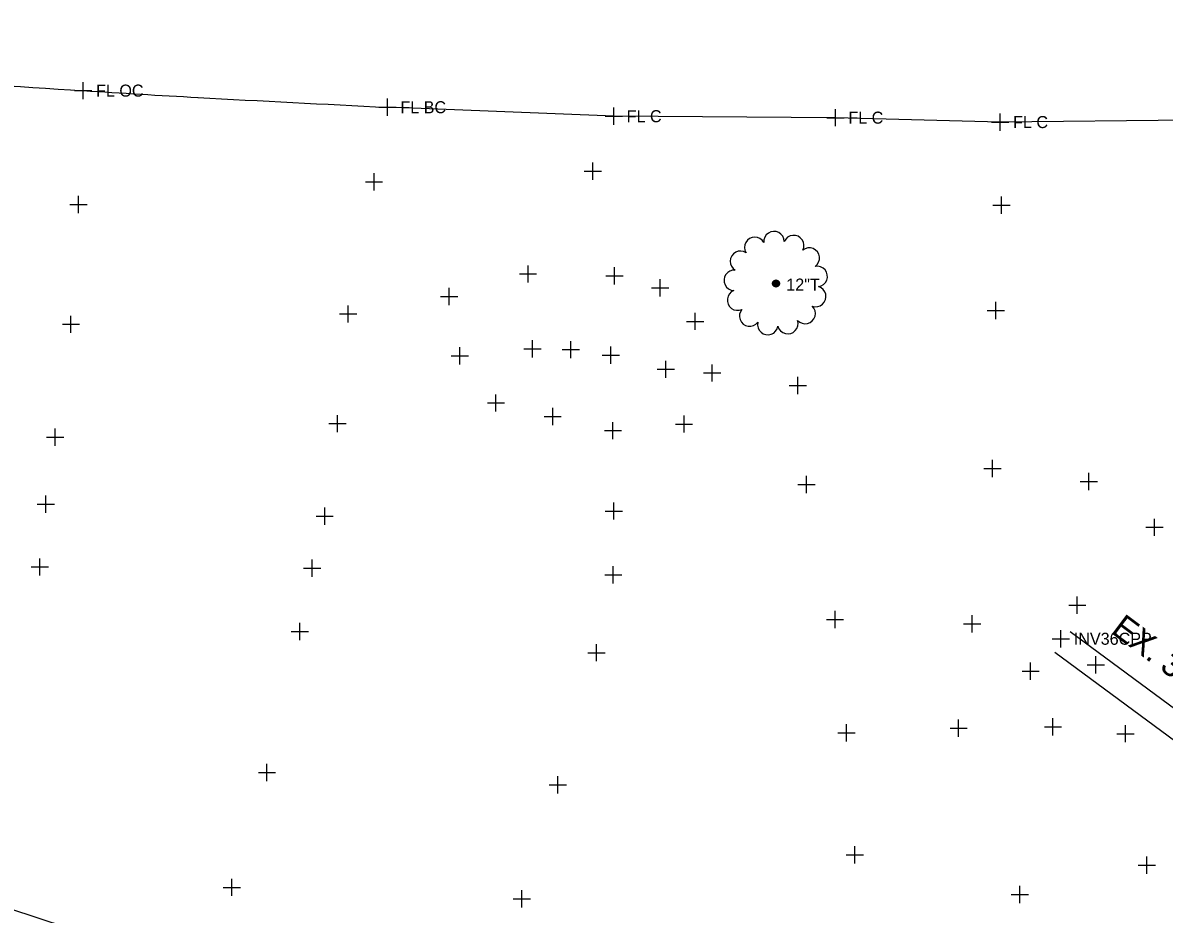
# Model space of a CAD drawing. Extents: x 1324236 to 1326110, y 459090 to 460782.
# Drawn here: x 1325183.3 to 1325315.8, y 460409.8 to 460513.2 of the extents above; entities that cross this region are included whole.
import ezdxf

# ---------------------------------------------------------------- set-up
doc = ezdxf.new("R2010")
doc.units = 0
for name, color, linetype in [('DV_X_Property_Line', 7, 'Continuous'), ('PM_X_CL_Double_Solid', 7, 'Continuous'), ('PV_X_Shoulder_Aggregate', 7, 'Continuous'), ('RW_X_CL', 7, 'Continuous'), ('RW_X_Esmt_SH', 7, 'Continuous'), ('UT_X_Telecom', 7, 'Continuous'), ('VG_X_Cells', 7, 'Continuous'), ('VG_X_Flower_Bed', 7, 'Continuous')]:
    doc.layers.add(name, color=color, linetype=linetype)

msp = doc.modelspace()

# ---------------------------------------------------------------- linework, layer by layer
at = {"layer": 'DV_X_Property_Line'}
for p, q in [((1325303.82, 460440.73), (1325303.82, 460442.73)), ((1325302.82, 460441.73), (1325304.82, 460441.73))]:
    msp.add_line(p, q, dxfattribs=at)
at = {"layer": 'PM_X_CL_Double_Solid'}
for p, q in [((1325251.91, 460502.37), (1325225.64, 460503.41)), ((1325277.65, 460502.2), (1325251.91, 460502.37)), ((1325296.77, 460501.69), (1325277.65, 460502.2)), ((1325326.93, 460502), (1325296.77, 460501.69))]:
    msp.add_line(p, q, dxfattribs=at)
for centre, radius, start, end in [((1333068.62, 583041.15), 122788.82, 266.3103858, 266.3212962), ((1325279.09, 461886.04), 1383.55, 266.3213, 266.87412), ((1325409.07, 464266.24), 3767.3, 266.87412, 267.20913)]:
    msp.add_arc(centre, radius, start, end, dxfattribs=at)
at = {"layer": 'PV_X_Shoulder_Aggregate'}
msp.add_lwpolyline([(1325286.15, 460376.13), (1325267.35, 460382.9), (1325236.36, 460392.86), (1325205.04, 460402.74), (1325175.07, 460412.61), (1325145.55, 460421.9), (1325113.81, 460432.03), (1325082.13, 460441.54), (1325051.05, 460449.76), (1325019.35, 460459.28), (1324987.54, 460468.89), (1324956.75, 460477.62), (1324924.35, 460486.71), (1324893.18, 460495.82), (1324861.31, 460505.68), (1324828.49, 460513.21)], dxfattribs=at)
at = {"layer": 'RW_X_CL'}
for p, q in [((1325249.47, 460494.98), (1325249.47, 460496.98)), ((1325224.08, 460493.75), (1325224.08, 460495.75)), ((1325248.47, 460495.98), (1325250.47, 460495.98)), ((1325223.08, 460494.75), (1325225.08, 460494.75)), ((1325189.78, 460491.13), (1325189.78, 460493.13)), ((1325296.93, 460491.04), (1325296.93, 460493.04)), ((1325188.78, 460492.13), (1325190.78, 460492.13)), ((1325295.93, 460492.04), (1325297.93, 460492.04)), ((1325241.96, 460483.06), (1325241.96, 460485.06)), ((1325251.99, 460482.85), (1325251.99, 460484.85)), ((1325240.96, 460484.06), (1325242.96, 460484.06)), ((1325250.99, 460483.85), (1325252.99, 460483.85)), ((1325257.3, 460481.45), (1325257.3, 460483.45)), ((1325232.81, 460480.46), (1325232.81, 460482.46)), ((1325256.3, 460482.45), (1325258.3, 460482.45)), ((1325231.81, 460481.46), (1325233.81, 460481.46)), ((1325296.27, 460478.83), (1325296.27, 460480.83)), ((1325221.07, 460478.42), (1325221.07, 460480.42)), ((1325261.37, 460477.56), (1325261.37, 460479.56)), ((1325295.27, 460479.83), (1325297.27, 460479.83)), ((1325187.9, 460478.22), (1325189.9, 460478.22)), ((1325188.9, 460477.22), (1325188.9, 460479.22)), ((1325220.07, 460479.42), (1325222.07, 460479.42)), ((1325260.37, 460478.56), (1325262.37, 460478.56)), ((1325234.03, 460473.56), (1325234.03, 460475.56)), ((1325242.48, 460474.37), (1325242.48, 460476.37)), ((1325246.93, 460474.28), (1325246.93, 460476.28)), ((1325251.56, 460473.63), (1325251.56, 460475.63)), ((1325233.03, 460474.56), (1325235.03, 460474.56)), ((1325241.48, 460475.37), (1325243.48, 460475.37)), ((1325245.93, 460475.28), (1325247.93, 460475.28)), ((1325250.56, 460474.63), (1325252.56, 460474.63)), ((1325256.97, 460473), (1325258.97, 460473)), ((1325257.97, 460472), (1325257.97, 460474)), ((1325263.35, 460471.57), (1325263.35, 460473.57)), ((1325262.35, 460472.57), (1325264.35, 460472.57)), ((1325273.27, 460470.12), (1325273.27, 460472.12)), ((1325272.27, 460471.12), (1325274.27, 460471.12)), ((1325237.24, 460469.09), (1325239.24, 460469.09)), ((1325238.24, 460468.09), (1325238.24, 460470.09)), ((1325219.85, 460465.69), (1325219.85, 460467.69)), ((1325243.82, 460467.52), (1325245.82, 460467.52)), ((1325244.82, 460466.52), (1325244.82, 460468.52)), ((1325260.07, 460465.65), (1325260.07, 460467.65)), ((1325218.85, 460466.69), (1325220.85, 460466.69)), ((1325251.82, 460464.88), (1325251.82, 460466.88)), ((1325259.07, 460466.65), (1325261.07, 460466.65)), ((1325186.07, 460465.13), (1325188.07, 460465.13)), ((1325187.07, 460464.13), (1325187.07, 460466.13)), ((1325250.82, 460465.88), (1325252.82, 460465.88)), ((1325295.87, 460460.5), (1325295.87, 460462.5)), ((1325294.87, 460461.5), (1325296.87, 460461.5)), ((1325307.07, 460458.98), (1325307.07, 460460.98)), ((1325273.28, 460459.63), (1325275.28, 460459.63)), ((1325274.28, 460458.63), (1325274.28, 460460.63)), ((1325306.07, 460459.98), (1325308.07, 460459.98)), ((1325185.97, 460456.34), (1325185.97, 460458.34)), ((1325184.97, 460457.34), (1325186.97, 460457.34)), ((1325218.35, 460454.96), (1325218.35, 460456.96)), ((1325251.93, 460455.55), (1325251.93, 460457.55)), ((1325217.35, 460455.96), (1325219.35, 460455.96)), ((1325250.93, 460456.55), (1325252.93, 460456.55)), ((1325314.68, 460453.66), (1325314.68, 460455.66)), ((1325313.68, 460454.66), (1325315.68, 460454.66)), ((1325185.29, 460449.06), (1325185.29, 460451.06)), ((1325216.91, 460448.91), (1325216.91, 460450.91)), ((1325184.29, 460450.06), (1325186.29, 460450.06)), ((1325215.91, 460449.91), (1325217.91, 460449.91)), ((1325250.86, 460449.15), (1325252.86, 460449.15)), ((1325251.86, 460448.15), (1325251.86, 460450.15)), ((1325305.73, 460444.62), (1325305.73, 460446.62)), ((1325277.6, 460442.97), (1325277.6, 460444.97)), ((1325304.73, 460445.62), (1325306.73, 460445.62)), ((1325276.6, 460443.97), (1325278.6, 460443.97)), ((1325293.52, 460442.45), (1325293.52, 460444.45)), ((1325214.46, 460442.58), (1325216.46, 460442.58)), ((1325215.46, 460441.58), (1325215.46, 460443.58)), ((1325292.52, 460443.45), (1325294.52, 460443.45)), ((1325249.91, 460439.11), (1325249.91, 460441.11)), ((1325248.91, 460440.11), (1325250.91, 460440.11)), ((1325307.88, 460437.7), (1325307.88, 460439.7)), ((1325300.31, 460436.98), (1325300.31, 460438.98)), ((1325306.88, 460438.7), (1325308.88, 460438.7)), ((1325299.31, 460437.98), (1325301.31, 460437.98)), ((1325278.92, 460429.81), (1325278.92, 460431.81)), ((1325291.95, 460430.35), (1325291.95, 460432.35)), ((1325302.9, 460430.52), (1325302.9, 460432.52)), ((1325277.92, 460430.81), (1325279.92, 460430.81)), ((1325290.95, 460431.35), (1325292.95, 460431.35)), ((1325301.9, 460431.52), (1325303.9, 460431.52)), ((1325310.33, 460430.71), (1325312.33, 460430.71)), ((1325311.33, 460429.71), (1325311.33, 460431.71)), ((1325211.65, 460425.22), (1325211.65, 460427.22)), ((1325210.65, 460426.22), (1325212.65, 460426.22)), ((1325245.42, 460423.78), (1325245.42, 460425.78)), ((1325244.42, 460424.78), (1325246.42, 460424.78)), ((1325279.9, 460415.65), (1325279.9, 460417.65)), ((1325278.9, 460416.65), (1325280.9, 460416.65)), ((1325313.81, 460414.45), (1325313.81, 460416.45)), ((1325312.81, 460415.45), (1325314.81, 460415.45)), ((1325207.56, 460411.88), (1325207.56, 460413.88)), ((1325206.56, 460412.88), (1325208.56, 460412.88)), ((1325241.24, 460410.56), (1325241.24, 460412.56)), ((1325298.05, 460412.05), (1325300.05, 460412.05)), ((1325299.05, 460411.05), (1325299.05, 460413.05)), ((1325240.24, 460411.56), (1325242.24, 460411.56))]:
    msp.add_line(p, q, dxfattribs=at)
at = {"layer": 'RW_X_Esmt_SH'}
for p, q in [((1325190.31, 460504.34), (1325190.31, 460506.34)), ((1325189.31, 460505.34), (1325191.31, 460505.34)), ((1325224.64, 460503.41), (1325226.64, 460503.41)), ((1325225.64, 460502.41), (1325225.64, 460504.41)), ((1325251.91, 460501.37), (1325251.91, 460503.37)), ((1325250.91, 460502.37), (1325252.91, 460502.37)), ((1325276.65, 460502.2), (1325278.65, 460502.2)), ((1325277.65, 460501.2), (1325277.65, 460503.2)), ((1325296.77, 460500.69), (1325296.77, 460502.69)), ((1325295.77, 460501.69), (1325297.77, 460501.69))]:
    msp.add_line(p, q, dxfattribs=at)
at = {"layer": 'VG_X_Cells'}
for points in [[(1325270.38, 460483.16), (1325270.74, 460482.96), (1325270.74, 460482.96), (1325270.33, 460482.96)], [(1325270.33, 460482.96), (1325270.74, 460482.96), (1325270.74, 460482.96), (1325270.38, 460482.75)], [(1325270.54, 460483.32), (1325270.74, 460482.96), (1325270.74, 460482.96), (1325270.38, 460483.16)], [(1325270.38, 460482.75), (1325270.74, 460482.96), (1325270.74, 460482.96), (1325270.54, 460482.6)], [(1325270.74, 460483.37), (1325270.74, 460482.96), (1325270.74, 460482.96), (1325270.54, 460483.32)], [(1325270.54, 460482.6), (1325270.74, 460482.96), (1325270.74, 460482.96), (1325270.74, 460482.55)], [(1325270.95, 460483.32), (1325270.74, 460482.96), (1325270.74, 460482.96), (1325270.74, 460483.37)], [(1325271.1, 460483.16), (1325270.74, 460482.96), (1325270.74, 460482.96), (1325270.95, 460483.32)], [(1325271.15, 460482.96), (1325270.74, 460482.96), (1325270.74, 460482.96), (1325271.1, 460483.16)], [(1325270.74, 460482.55), (1325270.74, 460482.96), (1325270.74, 460482.96), (1325270.95, 460482.6)], [(1325270.95, 460482.6), (1325270.74, 460482.96), (1325270.74, 460482.96), (1325271.1, 460482.75)], [(1325271.1, 460482.75), (1325270.74, 460482.96), (1325270.74, 460482.96), (1325271.15, 460482.96)]]:
    msp.add_lwpolyline(points, close=True, dxfattribs=at)
for centre, start, end in [((1325270.51, 460487.81), 1.241, 184.1237), ((1325268.28, 460487.15), 28.9333, 211.816), ((1325272.8, 460487.36), 333.5487, 156.4314), ((1325266.62, 460485.53), 56.6256, 239.5083), ((1325274.61, 460485.9), 305.8564, 128.7391), ((1325275.53, 460483.77), 278.1641, 101.0468), ((1325265.9, 460483.32), 84.3179, 267.2006), ((1325266.28, 460481.03), 112.0103, 294.8929), ((1325275.36, 460481.45), 250.4718, 73.3545), ((1325267.69, 460479.18), 139.7026, 322.5852), ((1325274.13, 460479.48), 222.7795, 45.6622), ((1325269.8, 460478.19), 167.3949, 350.2776), ((1325272.12, 460478.3), 195.0872, 17.9699)]:
    msp.add_arc(centre, 1.19, start, end, dxfattribs=at)
at = {"layer": 'VG_X_Flower_Bed'}
for p, q in [((1325304.91, 460442.59), (1325427.5, 460351.85)), ((1325303.12, 460440.18), (1325425.72, 460349.44))]:
    msp.add_line(p, q, dxfattribs=at)

# ---------------------------------------------------------------- texts
at = {"layer": 'DV_X_Property_Line'}
msp.add_text('INV36CPP', height=1.4, dxfattribs=at).set_placement((1325305.32, 460441.03))
at = {"layer": 'RW_X_Esmt_SH'}
for s, p in [('FL OC', (1325191.81, 460504.64)), ('FL BC', (1325227.14, 460502.71)), ('FL C', (1325253.41, 460501.67)), ('FL C', (1325279.15, 460501.5)), ('FL C', (1325298.27, 460500.99))]:
    msp.add_text(s, height=1.4, dxfattribs=at).set_placement(p)
at = {"layer": 'UT_X_Telecom'}
msp.add_text('EX. 36" CPP', height=2.8, rotation=323.0615, dxfattribs=at).set_placement((1325309.52, 460442.49))
at = {"layer": 'VG_X_Cells'}
msp.add_text('12"T', height=1.4, dxfattribs=at).set_placement((1325271.94, 460482.13))

doc.saveas('drawing.dxf')
